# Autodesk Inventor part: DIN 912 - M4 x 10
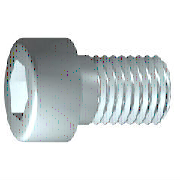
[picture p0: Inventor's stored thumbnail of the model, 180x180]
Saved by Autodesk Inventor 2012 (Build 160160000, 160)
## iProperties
Created: 2004-10
Part Number: DIN 912 - M4 x 10
Material: Standard
Description: Zylinderschraube
Vendor: Autodesk Inc.
Document SubType Name: Modeling
Standard: DIN 912
Designer: Administrator
Size Designation: M4 x 10
Density: 1 g/cm^3
Checked By: Jürgen Kronas
Stock Number: 10-10020
Company: CAD-Verlag
EGR: 1
Classification: un/spsc 31161501
Author: Juergen Kronas
Revision Number: 8
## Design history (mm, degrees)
revolve "Körper" stored, may be unused: angle "d10" = 90 deg
sketch "Skizze2"
  geometry: L1 (0, -4.2)-(0, 5.6) reference; L2 (-4.2, 0)-(5.6, 0) reference; L3 (1.732, 0)-(0.866, -1.5); L4 (0.866, -1.5)-(-0.866, -1.5); L5 (-0.866, -1.5)-(-1.732, 0); L6 (-1.732, 0)-(-0.866, 1.5); L7 (-0.866, 1.5)-(0.866, 1.5); L8 (0.866, 1.5)-(1.732, 0); 2 further points
  constraints: 12 end point, 1 coincident, 1 horizontal alignment, 1 point on line, 12 other
extrude "Loch" join sketch "Skizze2" stored distance "d11" = 10; taper "d12" = 0 deg
node "Volumenkörper1"
node "Volumenkörpern"
node "Oberflächenkörpern"
fillet "Rundung1" dims "d17" = 0.4 (= RR)
feature "Gewinde" dims "d13" = 8.25 (= GEL), "d14" = 0
chamfer "Fase1" distance "d15" = 0.42941 (= -0.5 x SPD + 0.5 x GD); stored, may be unused: second distance "d16" = 0.42941 (= GUL), angle "d27" = 45 deg
sketch "Skizze1"
  geometry: L1 (-1, 0)-(10, 0); L2 (10, 0)-(10, 2); L3 (10, 2)-(1.75, 2); L4 (1.75, 2)-(1.32, 2); L5 (1.32, 2)-(0, 2); L6 (0, 2)-(0, 3.5); L7 (0, 3.5)-(-4, 3.5); L8 (-4, 3.5)-(-4, 1.732); L9 (-4, 1.732)-(-2, 1.732); L10 (-2, 1.732)-(-1, 0); L11 (-15.5, 0)-(61.5, 0) reference; L12 (0, -0.8)-(0, 10.4) reference; L13 (1.75, 2)-(0, 2)
  constraints: 22 end point, 6 parallel, 2 collinear, 2 perpendicular, 1 horizontal, 1 point on line
  dimensions: "d1" = 8.25 distance from line of L3.end L2 (= GEL); "d2" = 0.42952 distance of L4.end L3.end (computed from GAL); "d3" = 4 distance between parallel lines of L8 L6 (= KOH); "d4" = 2 distance of L8.end L9.end (= INTI); "d5" = 60 deg angle of L10 L1; "d6" = 4 diameter of L3 L1 (= GD); "d7" = 4 diameter of L5 L1 (= BDM); "d8" = 3.4641 diameter of L9 L1 (= 1.1547 x SW); "d9" = 7 diameter of L7 L1 (= KOD); "d26" = 10 distance between parallel lines of L12 L2 (= NLG)
other parameters: "GD" = 4 (= NND) [user parameter; used in 2 equation terms], "NLG" = 10 [user parameter; used in 1 equation term], "GEL" = 8.25 [user parameter; used in 2 equation terms], "KOD" = 7 [user parameter; used in 1 equation term], "KOH" = 4 [user parameter; used in 2 equation terms], "INTI" = 2 [user parameter; used in 1 equation term], "GAL" = 0.42941 (= 0.61345 x TPU) [user parameter; used in 1 equation term], "GUL" = 0.42941 (= 0.61345 x TPU) [user parameter; used in 1 equation term], "BDM" = 4 (= NND) [user parameter; used in 1 equation term], "SW" = 3 [user parameter; used in 2 equation terms], "RR" = 0.4 (= 0.1 x KOH) [user parameter; used in 1 equation term], "SPD" = 3.14117 (= NND - 1.2269 x TPU) [user parameter; used in 1 equation term], "d18" = 0, "d19" = 0, "NND" = 4 [user parameter; used in 3 equation terms], "E0" = 3.465 (= 1.155 x SW) [user parameter], "ANG" = 120 deg [user parameter], "FAWI" = 45 deg [user parameter], "THREADDIA" = 4 [user parameter; used in 1 equation term], "TPU" = 0.7 [user parameter; used in 5 equation terms], "GD1" = 3.14117 (= THREADDIA - 1.2269 x TPU) [user parameter], "PTC" = 0.7 (= TPU) [user parameter], "TOA" = 30 deg [user parameter]
